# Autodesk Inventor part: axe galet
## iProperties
Shininess: 64.0
Length Units: 11269
Angle Units: 11279
Time Units: 11290
Mass Units: 11283
Length Display Precision: 3
Angle Display Precision: 2
Compacted: True
Part Number: axe galet
Document SubType Name: Modeling
Created: 2005-02
Material: Par défaut
Designer: LEGERET Philippe
Density: 0.0
Volumn: 0.0
Area: 0.0
PropertySet Name: Model Information
Control State: 0
Master: False
Checked Out: False
Author: LEGERET Philippe
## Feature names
1. Révolution1 [Revolution]
2. Chanfrein1 [Chamfer]
3. Chanfrein2 [Chamfer]
